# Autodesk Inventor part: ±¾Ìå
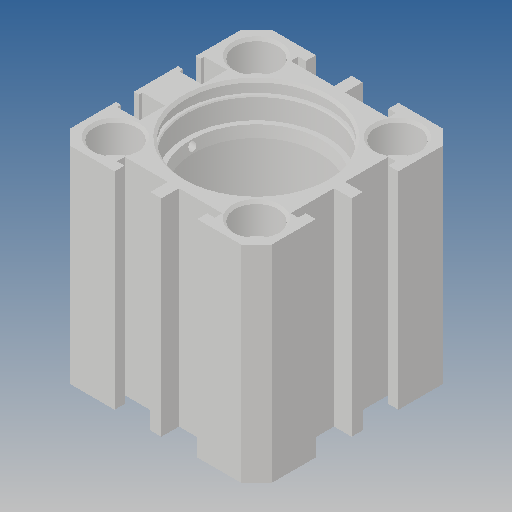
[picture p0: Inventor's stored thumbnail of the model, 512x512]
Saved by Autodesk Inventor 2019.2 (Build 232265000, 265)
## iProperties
Created: 2013-07
Part Number: ±¾Ìå
Material: Ogólny
Document SubType Name: Modeling
Designer: CADENGINEERING4
Density: 1 g/cm^3
Appearance: Domyślna
Author: CADENGINEERING4
Revision Number: ÈÎºÎ
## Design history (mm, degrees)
feature "ÇÐ³ý-À­Éì7"
node "Bryła1"
